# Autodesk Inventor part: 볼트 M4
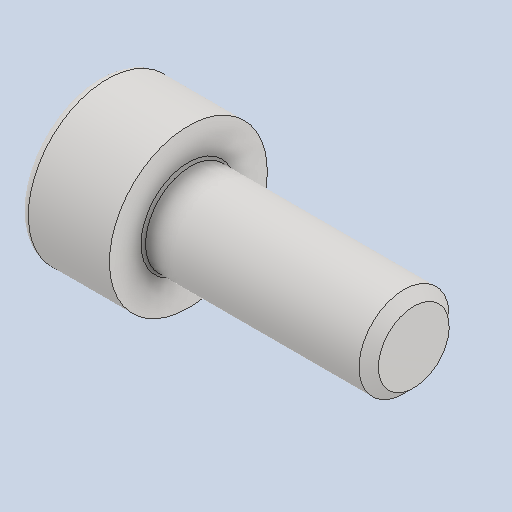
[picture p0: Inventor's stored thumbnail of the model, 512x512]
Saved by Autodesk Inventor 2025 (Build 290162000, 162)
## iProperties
Created: 2024-08
Part Number: 볼트 M4
Material: 스테인리스강
Description: 6각머리 태핑 나사
Document SubType Name: Modeling
Designer: rese9
Density: 8.08 g/cm^3
Appearance: 기본값
Author: jhkim
Sending System: Autodesk Inventor 2025
Preprocessor: ST-DEVELOPER v20
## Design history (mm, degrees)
feature "Solid1"
node "솔리드1"
